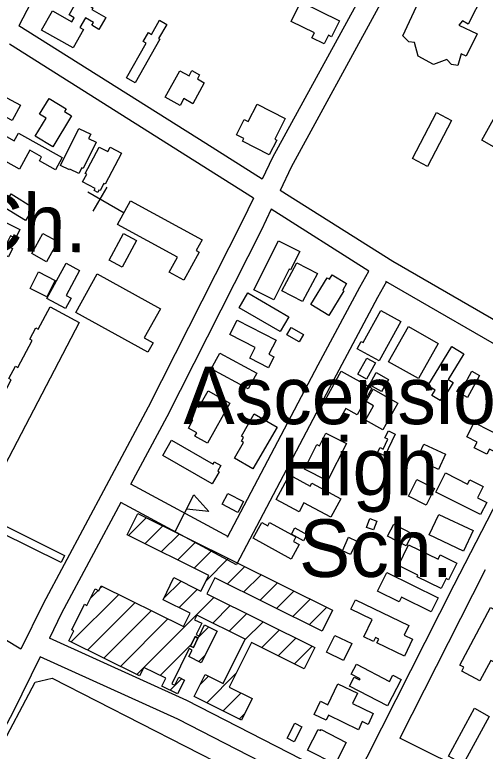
# Model space of a CAD drawing. Extents: x 3361039 to 3398939, y 576572 to 602007.
# Drawn here: x 3390761 to 3391439, y 582476 to 583538 of the extents above; entities that cross this region are included whole.
import ezdxf

# ---------------------------------------------------------------- set-up
doc = ezdxf.new("R2010")
doc.units = 0
for name, color, linetype in [('V-BLDG-IDEN', 7, 'Continuous'), ('V-BLDG-OTLN', 7, 'Continuous'), ('V-RIVR-EDGE', 7, 'Continuous'), ('V-ROAD-CNTR', 7, 'Continuous'), ('V-SITE-OTLN', 7, 'Continuous'), ('V-SITE-OTLN-IDEN', 7, 'Continuous')]:
    doc.layers.add(name, color=color, linetype=linetype)

msp = doc.modelspace()

# ---------------------------------------------------------------- linework, layer by layer
at = {"layer": 'V-BLDG-OTLN'}
for p, q in [((3390991.8, 582792.2), (3391018.9, 582845.7)), ((3390924.8, 582787.1), (3390950.4, 582812.7)), ((3390948.4, 582775.3), (3390974, 582800.9)), ((3390972.1, 582763.6), (3390997.7, 582789.2)), ((3390995.7, 582751.9), (3391021.3, 582777.5)), ((3391019.3, 582740.1), (3391044.9, 582765.7)), ((3391036.6, 582722.1), (3391068.5, 582754)), ((3391067.1, 582717.3), (3391092.2, 582742.3)), ((3391090.8, 582705.5), (3391115.8, 582730.5)), ((3390883.3, 582710.2), (3390887.2, 582714.1)), ((3390975.4, 582696.2), (3391000.6, 582721.4)), ((3391114.4, 582693.8), (3391139.4, 582718.8)), ((3390870.2, 582697.1), (3390881.2, 582708.1)), ((3390997.7, 582683.2), (3391024.2, 582709.7)), ((3391138, 582682.1), (3391163, 582707.1)), ((3390842.2, 582633.7), (3390910.8, 582702.4)), ((3390947, 582597.1), (3391047.9, 582698)), ((3391161.6, 582670.3), (3391186.6, 582695.3)), ((3390865.8, 582622), (3390934.4, 582690.6)), ((3391046.2, 582660.9), (3391071.6, 582686.3)), ((3391185.2, 582658.6), (3391210.3, 582683.6)), ((3390889.4, 582610.3), (3390958.1, 582678.9)), ((3391069.8, 582649.2), (3391095.2, 582674.6)), ((3390913.1, 582598.5), (3390981.7, 582667.1)), ((3391092, 582636.1), (3391118.8, 582662.8)), ((3391024.5, 582639.2), (3391040.6, 582655.4)), ((3391116.7, 582625.4), (3391142.4, 582651.1)), ((3391140.4, 582613.7), (3391166, 582639.4)), ((3390970.6, 582585.4), (3391015.1, 582629.9)), ((3391164, 582602), (3391189.7, 582627.6)), ((3391026.2, 582605.6), (3391035.2, 582614.6)), ((3390936.7, 582586.8), (3390947, 582597.1)), ((3391037.5, 582546.2), (3391080.1, 582588.8)), ((3390984.8, 582564.2), (3391001.3, 582580.7)), ((3391028.2, 582572.3), (3391040.3, 582584.4)), ((3391061.1, 582534.5), (3391087, 582560.3)), ((3391084.8, 582522.8), (3391092.4, 582530.4))]:
    msp.add_line(p, q, dxfattribs=at)
msp.add_lwpolyline([(3391435.9, 583567.3), (3391414.1, 583524.5), (3391406.2, 583529.3), (3391401.1, 583523), (3391427.3, 583510.4), (3391411.4, 583478.2), (3391404.1, 583481.9), (3391399.5, 583465), (3391390.2, 583466.4), (3391383.6, 583473.8), (3391364.4, 583466.2), (3391342.5, 583478.4), (3391337.2, 583498), (3391329, 583498.9), (3391320.1, 583507.8), (3391342.9, 583556.3)], dxfattribs=at)
for points in [[(3390844.9, 583490.3), (3390799.7, 583516.1), (3390815.5, 583543.7), (3390843.1, 583527.9), (3390846.5, 583533.9), (3390839.2, 583538.1), (3390852, 583560.6), (3390873.6, 583548.2), (3390872.1, 583545.5), (3390892, 583534.1), (3390882.3, 583517), (3390872.1, 583522.9), (3390874.4, 583527), (3390862.9, 583533.6), (3390854.9, 583519.7), (3390860.1, 583516.7)], [(3391173.4, 583556.9), (3391229.1, 583529.6), (3391217.6, 583506.3), (3391213.1, 583508.5), (3391207, 583496), (3391189.2, 583504.7), (3391192.8, 583512.2), (3391159.5, 583528.6)], [(3390922, 583447.2), (3390950.2, 583497.1), (3390946.2, 583499.4), (3390953.5, 583512.3), (3390958.2, 583509.7), (3390969.7, 583530.1), (3390979.9, 583524.3), (3390968.2, 583503.8), (3390969.8, 583502.9), (3390934.3, 583440.2)], [(3390977.9, 583419.1), (3390998.7, 583457.5), (3391012.2, 583450.2), (3391016.2, 583457.6), (3391027.4, 583451.5), (3391024.1, 583445.5), (3391034.1, 583440), (3391017.8, 583409.9), (3391004.4, 583417.2), (3390999.2, 583407.5)], [(3390742.3, 583422), (3390769, 583407.7), (3390757.2, 583385.6), (3390730.5, 583399.8)], [(3390796.8, 583394.6), (3390810.4, 583417.2), (3390835, 583402.4), (3390832.5, 583398.4), (3390842.7, 583392.3), (3390815.9, 583347.8), (3390790.5, 583363.1), (3390806.1, 583389)], [(3391433.9, 583357.2), (3391467.3, 583417), (3391484.9, 583407.2), (3391451.6, 583347.4)], [(3391097.3, 583384.2), (3391110.1, 583409.4), (3391150.8, 583388.6), (3391135.6, 583358.8), (3391138.5, 583357.3), (3391127.7, 583336.1), (3391089, 583355.8), (3391090.9, 583359.5), (3391080.4, 583364.9), (3391091.6, 583387.1)], [(3391334.1, 583330.8), (3391368.5, 583397.1), (3391390.2, 583385.8), (3391355.9, 583319.5)], [(3390767.7, 583315.7), (3390716.1, 583344.3), (3390723.2, 583357.2), (3390718, 583360.1), (3390725.3, 583373.3), (3390730, 583370.7), (3390731, 583372.6), (3390760.1, 583356.4), (3390766.3, 583367.6), (3390829.5, 583332.5), (3390819.7, 583314.7), (3390796.4, 583327.6), (3390799.6, 583333.5), (3390782.8, 583342.8)], [(3390826.9, 583320.8), (3390853.4, 583374.2), (3390870.4, 583365.8), (3390867.4, 583359.8), (3390878.3, 583354.4), (3390859.6, 583316.5), (3390857.6, 583317.5), (3390853.4, 583309), (3390840.2, 583315.5), (3390839.6, 583314.4)], [(3390862.6, 583309.3), (3390882.7, 583347.3), (3390895.1, 583340.8), (3390898.6, 583347.4), (3390914.9, 583338.7), (3390891.2, 583293.9), (3390889.4, 583294.9), (3390883.9, 583284.5), (3390882.3, 583285.4), (3390880.5, 583282), (3390875.2, 583284.8), (3390876.7, 583287.5), (3390858.6, 583297.1), (3390864.6, 583308.3)], [(3390755.8, 583279.9), (3390788.1, 583259.8), (3390776.5, 583241.3), (3390744.2, 583261.4)], [(3390927.7, 583269.7), (3391030.8, 583213.4), (3391022.4, 583198.1), (3391026.5, 583195.9), (3391004.4, 583155.4), (3390983.4, 583166.8), (3390995.3, 583188.7), (3390909.1, 583235.7)], [(3390700.7, 583262.7), (3390711.5, 583257.3), (3390713.2, 583260.5), (3390721.2, 583256.5), (3390719.5, 583253.1), (3390768.5, 583228.4), (3390762, 583215.6), (3390754.9, 583219.2), (3390748.2, 583205.9), (3390757.9, 583201), (3390751.9, 583189.1), (3390681.5, 583224.7)], [(3390785.4, 583193.7), (3390801.4, 583222.9), (3390822.9, 583211.1), (3390806.8, 583181.9)], [(3390896.9, 583184.2), (3390917.8, 583222.6), (3390936.4, 583212.5), (3390915.5, 583174)], [(3391105.5, 583141.7), (3391141.2, 583212.2), (3391171.7, 583196.7), (3391158.3, 583170.4), (3391156.5, 583171.3), (3391134.2, 583127.2)], [(3390807.2, 583129), (3390834.8, 583179.8), (3390854.4, 583169.2), (3390834.9, 583133.2), (3390842.1, 583129.3), (3390834, 583114.4)], [(3391146, 583140.2), (3391167.3, 583180.6), (3391197, 583165), (3391175.6, 583124.5)], [(3390783.2, 583143.6), (3390795.1, 583167.2), (3390819, 583155.1), (3390807.1, 583131.6)], [(3390879.7, 583164.6), (3390970.8, 583114.3), (3390947.6, 583072.3), (3390960.4, 583065.3), (3390952.8, 583051.4), (3390848.9, 583108.8)], [(3391187.5, 583120.1), (3391211.1, 583158.8), (3391214.7, 583156.7), (3391218.5, 583163), (3391239.2, 583150.5), (3391233.5, 583141.2), (3391235.2, 583140.2), (3391213.4, 583104.3)], [(3391096.8, 583137.2), (3391155.7, 583102.7), (3391143.2, 583081.3), (3391084.3, 583115.7)], [(3390853.8, 583094.2), (3390710.3, 582819.3), (3390832.7, 582758.6), (3390827.6, 582748.3), (3390696.4, 582813.4), (3390705.4, 582831.3), (3390670, 582849.2), (3390730.7, 582963.7), (3390727.6, 582965.1), (3390733.7, 582977), (3390736.5, 582975.6), (3390755.9, 583011.9), (3390752.6, 583013.6), (3390762.2, 583031.5), (3390765.4, 583029.7), (3390786.2, 583068.5), (3390782.5, 583070.5), (3390791.2, 583086.7), (3390794.7, 583084.8), (3390812.1, 583117.2)], [(3391263.2, 583065.4), (3391288.3, 583111.7), (3391317.2, 583096), (3391286.3, 583039.2), (3391254.4, 583056.5), (3391260.1, 583067)], [(3391081.3, 583097.8), (3391137.7, 583068.8), (3391127.3, 583048.6), (3391134.5, 583044.9), (3391126.4, 583029.2), (3391099.5, 583043), (3391107.5, 583058.5), (3391070.8, 583077.3)], [(3391159.2, 583087.3), (3391176.8, 583077.3), (3391170.6, 583066.5), (3391153.1, 583076.5)], [(3391299.7, 583037.8), (3391328.2, 583088.5), (3391371.1, 583064.3), (3391342.7, 583013.6)], [(3391356, 583003.2), (3391390.6, 583059.7), (3391408, 583049.1), (3391385.5, 583012.4), (3391392.9, 583007.8), (3391380.4, 582987.3), (3391378.2, 582988.6), (3391374.2, 582982), (3391362.2, 582989.3), (3391366.7, 582996.7)], [(3391097.2, 582998.6), (3391044, 583027.8), (3391056.4, 583050.4), (3391109.6, 583021.1)], [(3391255.3, 583019.9), (3391268.4, 583043.1), (3391281, 583036), (3391267.9, 583012.8)], [(3391197.6, 582963), (3391231.5, 583024.1), (3391275.5, 582999.7), (3391254.3, 582961.4), (3391237.8, 582970.5), (3391225.1, 582947.7)], [(3391272, 583004.5), (3391281.7, 583022.1), (3391299.3, 583012.4), (3391289.6, 582994.8)], [(3391406.4, 583000.3), (3391419.6, 583024.2), (3391430.7, 583018.2), (3391413.3, 582986.3), (3391397.8, 582994.8), (3391402.1, 583002.6)], [(3391071.1, 582977.9), (3391038.5, 582920.2), (3391020.3, 582930.5), (3391023.1, 582935.5), (3391011.3, 582942.2), (3391017.8, 582953.8), (3391012.9, 582956.6), (3391022.8, 582974.2), (3391026.2, 582972.3), (3391039.5, 582995.7)], [(3391277.4, 582998.1), (3391313.1, 582978), (3391291.5, 582939.5), (3391266.3, 582953.6), (3391278, 582974.4), (3391267.4, 582980.3)], [(3391139, 582943.5), (3391104.2, 582883.3), (3391077.6, 582898.7), (3391090.6, 582921.3), (3391087.6, 582923.1), (3391090.8, 582928.7), (3391087.5, 582930.6), (3391106, 582962.6)], [(3391423.2, 582950.2), (3391490.5, 582915.5), (3391479.4, 582893.9), (3391445, 582911.6), (3391441.2, 582904.4), (3391423.2, 582913.7), (3391427.4, 582921.8), (3391412.5, 582929.4)], [(3391294.4, 582928.1), (3391299.4, 582938.2), (3391309.3, 582933.4), (3391294, 582902.1), (3391283.9, 582907), (3391287.3, 582914.1), (3391291.8, 582911.9), (3391298.7, 582926)], [(3391178.3, 582882.8), (3391196.2, 582918.5), (3391200.2, 582916.4), (3391209.4, 582934.7), (3391238.8, 582920), (3391211.8, 582866)], [(3390987, 582924.6), (3391046.8, 582890.3), (3391048.5, 582893.3), (3391057.9, 582888), (3391053.5, 582880.3), (3391055.5, 582879.1), (3391045.5, 582861.6), (3390974.3, 582902.4)], [(3391350.2, 582918.9), (3391381.6, 582904.7), (3391371.6, 582882.5), (3391359.4, 582888), (3391362.2, 582894.2), (3391356.4, 582896.8), (3391358, 582900.5), (3391344.7, 582906.5)], [(3391156.9, 582874.7), (3391186.8, 582858.6), (3391189, 582862.7), (3391230.7, 582840.2), (3391216.3, 582813.6), (3391177.7, 582834.4), (3391170.6, 582821.3), (3391137.7, 582839.1)], [(3391432.3, 582817.3), (3391367.6, 582849.9), (3391381.6, 582877.6), (3391413.6, 582861.5), (3391416.6, 582867.5), (3391436, 582857.7), (3391427.9, 582841.7), (3391441.2, 582835)], [(3391340.5, 582867.8), (3391365.9, 582854.8), (3391353.7, 582830.9), (3391328.4, 582843.9)], [(3391018.9, 582845.7), (3391040.4, 582821.9), (3391008.4, 582825.1)], [(3391068, 582848), (3391090.4, 582836.3), (3391082.2, 582820.5), (3391059.8, 582832.2)], [(3391022.4, 582644.6), (3391026.5, 582642.2), (3391034.6, 582658.4), (3391052.6, 582649.4), (3391029.8, 582603.8), (3391011.8, 582612.8), (3391016.5, 582622.1), (3391012.3, 582624.3), (3390987.1, 582573.5), (3390991.5, 582571.4), (3390997.2, 582582.8), (3391005.4, 582578.7), (3390995.5, 582558.9), (3390972.9, 582570.1), (3390978.5, 582581.5), (3390947, 582597.1), (3390940.8, 582584.7), (3390839.1, 582635.3), (3390846.2, 582649.7), (3390843.2, 582651.2), (3390861.5, 582688.1), (3390864.9, 582686.4), (3390876.7, 582710.3), (3390882, 582707.6), (3390885.6, 582714.9), (3391004.1, 582656), (3391013.6, 582675.3), (3390974.6, 582694.7), (3390990.4, 582726.5), (3391029.2, 582707.2), (3391040.4, 582729.7), (3390922.9, 582788), (3390938.2, 582818.8), (3391218.7, 582679.4), (3391203.8, 582649.4), (3391049.4, 582726.1), (3391037.9, 582703), (3391193.2, 582625.9), (3391177.8, 582595.1), (3391101.9, 582632.8), (3391070.1, 582568.7), (3391103.2, 582552.2), (3391087.8, 582521.2), (3391019.7, 582555.1), (3391035.4, 582586.8), (3391061.2, 582574), (3391092.9, 582637.8), (3391023.4, 582672.3), (3391020.1, 582665.8), (3391030.4, 582660.7)], [(3391267.8, 582799), (3391272.4, 582811.7), (3391282.8, 582808), (3391278.1, 582795.2)], [(3391372.2, 582817.5), (3391421.5, 582794.3), (3391407.6, 582764.9), (3391358.3, 582788.1)], [(3391127.9, 582806), (3391166.1, 582785.2), (3391162.6, 582778.7), (3391170.8, 582774.2), (3391159.5, 582753.3), (3391104.4, 582783.3), (3391116.8, 582806.1), (3391125.4, 582801.4)], [(3391307.4, 582803.7), (3391334.1, 582789.8), (3391324.9, 582772.3), (3391298.2, 582786.2)], [(3391164.7, 582798.3), (3391182, 582788.8), (3391176.9, 582779.7), (3391159.7, 582789.2)], [(3391233.1, 582765.1), (3391242.1, 582784.7), (3391253.9, 582779.3), (3391244.8, 582759.7)], [(3391328.5, 582773.8), (3391371, 582753.1), (3391374, 582759.2), (3391397.9, 582747.6), (3391386.1, 582723.5), (3391382.6, 582725.2), (3391375.6, 582710.8), (3391340.7, 582727.8), (3391341.8, 582730.1), (3391314, 582744)], [(3391297.1, 582733.9), (3391371.1, 582697.5), (3391361.2, 582677.2), (3391318.2, 582698.4), (3391315, 582691.7), (3391283.9, 582707)], [(3391252, 582694.6), (3391328.8, 582657.7), (3391322, 582643.5), (3391334.3, 582637.6), (3391322.6, 582613.2), (3391282.9, 582632.3), (3391285.6, 582637.9), (3391280.7, 582640.3), (3391277.9, 582634.4), (3391263.9, 582641.2), (3391275.9, 582666.2), (3391245.4, 582680.9)], [(3391402.3, 582600.4), (3391446.7, 582683.2), (3391477.8, 582666.5), (3391462.3, 582637.5), (3391474.9, 582630.7), (3391458.8, 582600.7), (3391446.9, 582607), (3391431.3, 582577.8), (3391405.2, 582591.8), (3391408.1, 582597.3)], [(3391014.1, 582627.9), (3391020.8, 582641.4), (3391024.9, 582639), (3391018.3, 582625.7)], [(3391014.1, 582627.9), (3391018.3, 582625.7), (3391024.9, 582639), (3391020.8, 582641.4)], [(3391210.1, 582618.9), (3391222.1, 582643.3), (3391246.6, 582631.3), (3391234.7, 582606.9)], [(3391253.3, 582601.7), (3391301.2, 582576.7), (3391305.9, 582585.8), (3391317.8, 582579.6), (3391298.1, 582541.7), (3391243.4, 582570.1), (3391250.1, 582582.9), (3391257.6, 582579), (3391258.5, 582580.7), (3391245.8, 582587.3)], [(3391212.1, 582543.1), (3391226.7, 582573.3), (3391254.8, 582559.7), (3391247.6, 582544.8), (3391277.4, 582530.4), (3391270, 582514.9), (3391261.8, 582518.9), (3391256.2, 582507.2), (3391213, 582528), (3391209.6, 582520.9), (3391192.2, 582529.3), (3391201.3, 582548.3)], [(3391385.8, 582469.3), (3391423.6, 582538.1), (3391444.7, 582526.5), (3391406.9, 582457.7)], [(3391153.4, 582495), (3391164.5, 582516.6), (3391174.7, 582511.4), (3391163.6, 582489.8)], [(3391222.5, 582457.6), (3391183, 582477.9), (3391198.3, 582507.7), (3391201.5, 582506.1), (3391202.3, 582507.6), (3391238.6, 582488.9)]]:
    msp.add_lwpolyline(points, close=True, dxfattribs=at)
at = {"layer": 'V-RIVR-EDGE'}
msp.add_spline([(3387368.6, 585771), (3387389, 585767.6), (3387407.3, 585766.1), (3387418.2, 585761.7), (3387425.5, 585756.5), (3387441.6, 585752.8), (3387452.6, 585751.4), (3387462.1, 585753.9), (3387477.4, 585758.2), (3387482.9, 585759.3), (3387491.7, 585759.3), (3387502.3, 585758.2), (3387510.3, 585756.3), (3387521.6, 585753), (3387530.1, 585752.3), (3387538.5, 585752.2), (3387549.8, 585752.2), (3387558.9, 585755.5), (3387571.4, 585756.9), (3387583.4, 585757.3), (3387598.4, 585756.1), (3387629.8, 585749.5), (3387659.8, 585743.5), (3387703.3, 585736.8), (3387727.4, 585734.2), (3387739.1, 585733.5), (3387750.8, 585734.2), (3387753.7, 585731.6), (3387763.2, 585723.9), (3387774.5, 585720.6), (3387790.6, 585719.8), (3387800.1, 585721.6), (3387814, 585720.1), (3387824.6, 585720.1), (3387847.3, 585714.2), (3387884.2, 585709.4), (3387930.2, 585702.7), (3387980.6, 585701.1), (3388035.1, 585696.5), (3388076, 585694.6), (3388096.9, 585693.8), (3388120.3, 585690.5), (3388145.1, 585685.3), (3388171.8, 585682.3), (3388198.8, 585676.8), (3388222.6, 585669.4), (3388245.6, 585660.6), (3388260.9, 585655.4), (3388279.6, 585655.4), (3388291.3, 585658.3), (3388298.9, 585663.7), (3388299.3, 585666.3), (3388299, 585670.7), (3388290.6, 585674.4), (3388291.7, 585677.3), (3388293.9, 585678.4), (3388303, 585677.6), (3388318.7, 585676.5), (3388334.1, 585672.8), (3388354.1, 585663.6), (3388357.1, 585659.9), (3388363.3, 585658.1), (3388368.4, 585658.1), (3388371, 585661), (3388375.3, 585662.1), (3388379, 585661.3), (3388383, 585659.1), (3388383.7, 585654.4), (3388384.1, 585649.3), (3388389.9, 585647.4), (3388406, 585642.3), (3388468.9, 585637.7), (3388491.5, 585635.8), (3388534.6, 585628.4), (3388578.1, 585619.2), (3388610.6, 585613.6), (3388635.9, 585612.1), (3388727.9, 585599.4), (3388768.5, 585591.7), (3388822.6, 585580.9), (3388865, 585570.6), (3388906.6, 585562.8), (3388924.1, 585559.5), (3388938.8, 585562), (3388961.4, 585563.4), (3388974.2, 585560.1), (3389007.5, 585553.4), (3389018.8, 585554.5), (3389027.2, 585555.9), (3389037.1, 585555.9), (3389051.7, 585553.7), (3389061.2, 585553.3), (3389081.3, 585552.1), (3389098.1, 585551), (3389120.4, 585548.7), (3389143.4, 585546.5), (3389160.2, 585542.1), (3389200.8, 585534.7), (3389222.3, 585525.1), (3389247.2, 585519.2), (3389280.4, 585509.6), (3389307.5, 585497.8), (3389334.5, 585487.2), (3389349.5, 585483.1), (3389361.5, 585483.1), (3389382.7, 585479), (3389397, 585476.8), (3389416.7, 585468.7), (3389441.9, 585458.4), (3389464.9, 585451.4), (3389479.5, 585449.2), (3389506.2, 585446.2), (3389533.2, 585447.2), (3389558.5, 585444.2), (3389577.8, 585437.9), (3389603.4, 585431.3), (3389618.7, 585425.1), (3389639.2, 585415.1), (3389657.8, 585410.3), (3389693.2, 585404.8), (3389768.9, 585383), (3389806.5, 585373), (3389854.3, 585362.3), (3389881.7, 585358.6), (3389913.9, 585354.5), (3389953.7, 585349.3), (3390008.2, 585341.8), (3390037.8, 585336.3), (3390074.3, 585327.8), (3390128, 585312.7), (3390164.5, 585301.6), (3390200.7, 585289.8), (3390292.7, 585255.6), (3390327.1, 585241.3), (3390360.7, 585231.7), (3390404.5, 585221), (3390454.9, 585214.3), (3390483.1, 585210.5), (3390491.8, 585209.4), (3390494.4, 585207.2), (3390501.3, 585201), (3390507.9, 585200.6), (3390527.3, 585196.2), (3390545.9, 585195), (3390557.6, 585194.3), (3390574.4, 585189.8), (3390605.5, 585179.5), (3390698.6, 585148.2), (3390763.2, 585126.9), (3390811.1, 585111), (3390852.4, 585097.8), (3390900.9, 585081.6), (3390948.1, 585063.5), (3390993.7, 585048.4), (3391036.8, 585031.9), (3391070.8, 585020.1), (3391140.5, 584997.6), (3391201.5, 584974.1), (3391247.5, 584957.5), (3391310.7, 584933.6), (3391362.2, 584914.8), (3391400.6, 584900.1), (3391441.8, 584885.7), (3391505.4, 584861.1), (3391563.5, 584841.9), (3391658.8, 584807.3), (3391712.8, 584786), (3391758.8, 584767.3), (3391796.1, 584749.6), (3391880.4, 584718.3), (3391926.8, 584701.4), (3391969.2, 584685.2), (3392003.9, 584666.9), (3392040, 584650.3), (3392077.6, 584636), (3392135.7, 584613.2), (3392164.9, 584598.1), (3392196, 584583.8), (3392224.8, 584578.2), (3392263.5, 584567.9), (3392290.6, 584559.8), (3392322.7, 584546.5), (3392396.5, 584512.7), (3392439.9, 584496.2), (3392471.7, 584484.8), (3392502, 584473.3), (3392510.8, 584467.5), (3392535.2, 584458.3), (3392606.1, 584432.9), (3392632.4, 584421.5), (3392666.7, 584406.8), (3392715.6, 584386.9), (3392777.4, 584364.8), (3392827, 584348.3), (3392863.6, 584335.4), (3392897.9, 584321.8), (3392928.6, 584307.8), (3392965.4, 584294.9), (3393010, 584279.1), (3393054.6, 584263.2), (3393092.5, 584248.5), (3393195.2, 584206.6), (3393234.2, 584187.9), (3393264.5, 584173.5), (3393294.1, 584162.1), (3393336.8, 584147.4), (3393374.5, 584136.3), (3393402.2, 584127.5), (3393414.3, 584119.8), (3393435.4, 584109.1), (3393459.2, 584098.1), (3393478.9, 584087.5), (3393513.6, 584076.4), (3393541.7, 584067.2), (3393588.1, 584047.4), (3393643.2, 584028.9), (3393668.4, 584018.3), (3393699.8, 584005), (3393737.1, 583991.8), (3393781.7, 583976), (3393884.7, 583943.2), (3393927, 583928.8), (3393981.1, 583908.2), (3394043.9, 583885.4), (3394095.8, 583868.1), (3394154.9, 583847.1), (3394200.2, 583830.5), (3394247, 583816.2), (3394293, 583801.4), (3394349.6, 583781.2), (3394409.1, 583754.7), (3394451.8, 583730.5), (3394470.5, 583720.2), (3394481.8, 583715.4), (3394494.2, 583713.6), (3394502.6, 583708.1), (3394507.3, 583700.4), (3394511.3, 583697.8), (3394522.7, 583692.3), (3394557.3, 583675.8), (3394600.4, 583659.9), (3394658.1, 583638.9), (3394704.5, 583623.5), (3394760.4, 583607.6), (3394824, 583588.8), (3394867.8, 583570.8), (3394925.9, 583546.9), (3394972.2, 583528.9), (3394995.6, 583520), (3395064.7, 583504.2), (3395088.4, 583499.3), (3395120.2, 583491.6), (3395149.1, 583480.5), (3395173.2, 583476.8), (3395201.3, 583471.3), (3395236.4, 583459.9), (3395256.8, 583451.8), (3395280.9, 583445.5), (3395300.3, 583445.1), (3395316.7, 583440.7), (3395324.4, 583433.3), (3395335.3, 583426), (3395353.6, 583417.9), (3395398.9, 583403.9), (3395426.3, 583397.2), (3395442, 583391), (3395455.9, 583383.3), (3395476, 583377.8), (3395495.7, 583369.3), (3395511, 583368.2), (3395530.4, 583365.9), (3395550.5, 583361.8), (3395654.6, 583334.9), (3395704.7, 583322.4), (3395743.7, 583306.9), (3395765.3, 583295.5), (3395788.3, 583286.3), (3395816.4, 583278.9), (3395861.7, 583270.8), (3395916.2, 583261.5), (3395960.7, 583252.6), (3396008.6, 583242.6), (3396060.8, 583230.5), (3396093.4, 583222.3), (3396135.4, 583208.7), (3396170.1, 583199.8), (3396204.4, 583191.3), (3396254.8, 583177.3), (3396301.2, 583165.9), (3396364.4, 583152.9), (3396399.1, 583144.4), (3396426.9, 583138.5), (3396463.1, 583133), (3396489.8, 583132.9), (3396523.4, 583130.2), (3396607.8, 583114), (3396670.3, 583102.1), (3396708.3, 583095.4), (3396743, 583089.5), (3396775.1, 583083.9)], degree=3, dxfattribs=at)
at = {"layer": 'V-ROAD-CNTR'}
for p, q in [((3391068.8, 582785.2), (3390928.1, 582861.3)), ((3391080.5, 582744.8), (3390913.8, 582835))]:
    msp.add_line(p, q, dxfattribs=at)
for points in [[(3391556.4, 584085.6), (3391408.1, 583797.4), (3391384.4, 583729), (3391284.5, 583547.9), (3391159.2, 583318.5), (3391143.3, 583284.9)], [(3390901.4, 583780.9), (3390767, 583522.2)], [(3391267.7, 583579.5), (3391258.2, 583562.3), (3391132.4, 583332.1), (3391117.7, 583301)], [(3391117.7, 583301), (3391036.3, 583352.4), (3390767, 583522.2)], [(3391104.8, 583273.7), (3391020.3, 583327), (3390753.2, 583495.5)], [(3391560.5, 583039.2), (3391513, 583062.6), (3391306, 583182.2), (3391143.3, 583284.9)], [(3391104.8, 583273.7), (3391088.8, 583240), (3390953.3, 582972.1), (3390801.7, 582688.8), (3390769.6, 582623.3)], [(3391130.3, 583257.6), (3391115.8, 583226.8), (3390979.9, 582958.3), (3390927.7, 582860.7)], [(3391271.3, 583168.6), (3391130.3, 583257.6)], [(3391270.7, 583168.1), (3391257.6, 583144.7), (3391197.5, 583032.7), (3391067.1, 582784.5)], [(3391296.8, 583153.4), (3391283.9, 583130.3), (3391224, 583018.6), (3391080.3, 582745.2)], [(3391546.7, 583012.5), (3391498.8, 583036.1), (3391295.6, 583153.6)], [(3391546.7, 583012.5), (3391528.7, 582977.8), (3391393.7, 582715.4), (3391247.6, 582426.8)], [(3390769.6, 582623.3), (3390592.2, 582730.5), (3390408.1, 582842.2)], [(3390913.9, 582835), (3390828.4, 582675.1), (3390810.9, 582639.4)], [(3391439, 582737.7), (3391420.5, 582701.7), (3391315.7, 582494.9)], [(3391247.6, 582426.8), (3391008.9, 582549.2), (3390810.9, 582639.4)], [(3390797.7, 582612.4), (3390758.3, 582532), (3390625.1, 582282.5), (3390560.1, 582163.8), (3390488, 582023.4)], [(3391234, 582400), (3390995.9, 582522.2), (3390797.7, 582612.4)], [(3391546.4, 582380.1), (3391315.7, 582494.9)]]:
    msp.add_lwpolyline(points, dxfattribs=at)
at = {"layer": 'V-SITE-OTLN'}
for p, q in [((3390893.8, 583289.6), (3390873.7, 583254.9)), ((3390918.4, 583252.2), (3390866.4, 583282.3)), ((3390500.7, 582027), (3390790.3, 582575.9)), ((3390790.3, 582575.9), (3390815.1, 582581.5)), ((3390815.1, 582581.5), (3391098.1, 582437))]:
    msp.add_line(p, q, dxfattribs=at)

# ---------------------------------------------------------------- texts
at = {"layer": 'V-BLDG-IDEN'}
for s, p in [('Ascension', (3391003.9, 582947.8)), ('High', (3391142.9, 582845.3)), ('Sch.', (3391170.5, 582727.5))]:
    msp.add_text(s, height=83, dxfattribs=at).set_placement(p)
at = {"layer": 'V-SITE-OTLN-IDEN'}
msp.add_text('Ch.', height=83, rotation=359.4818, dxfattribs=at).set_placement((3390691.9, 583197.2))

doc.saveas('drawing.dxf')
